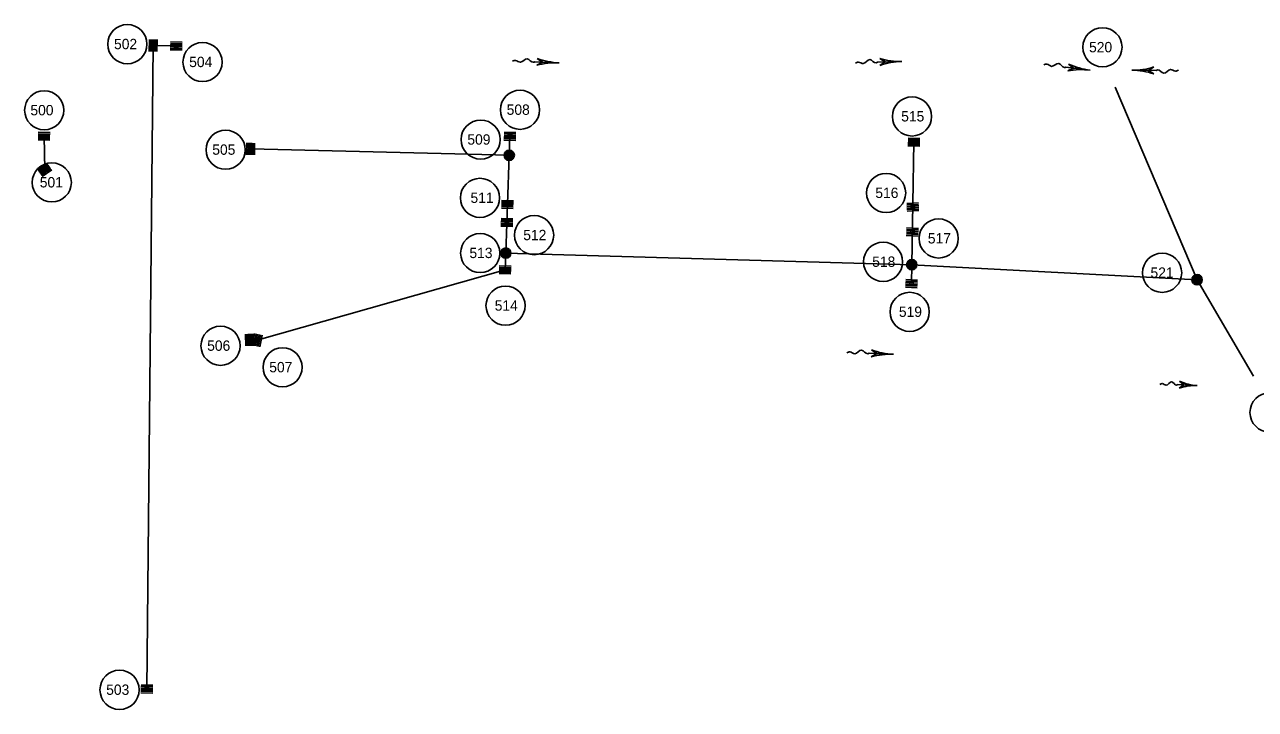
# Model space of a CAD drawing. Extents: x 594534 to 598564, y 225861 to 236229.
# Drawn here: x 594534 to 595247, y 230840 to 231238 of the extents above; entities that cross this region are included whole.
import ezdxf

# ---------------------------------------------------------------- set-up
doc = ezdxf.new("R2010")
doc.units = 0
for name, color, linetype in [('P_AREA', 7, 'Continuous'), ('P_DRN_Flow', 7, 'Continuous'), ('P_DRN_Inlet', 7, 'Continuous'), ('P_DRN_SS_MH', 7, 'Continuous'), ('P_DRN_SS_UG', 7, 'Continuous'), ('P_DRN_Text', 7, 'Continuous')]:
    doc.layers.add(name, color=color, linetype=linetype)

msp = doc.modelspace()

# ---------------------------------------------------------------- linework, layer by layer
at = {"layer": 'P_AREA'}
for p, q in [((594814.51, 231158.91), (594814.55, 231159.91)), ((594814.26, 231151.16), (594814.29, 231152.16))]:
    msp.add_line(p, q, dxfattribs=at)
at = {"layer": 'P_DRN_Flow'}
for p, q in [((594843.53, 231215.58), (594829.42, 231216.21)), ((595042.34, 231216.42), (595028.21, 231216.02)), ((595042.34, 231216.42), (595028.21, 231216.02)), ((595042.34, 231216.42), (595028.21, 231216.02)), ((595151.44, 231211.3), (595137.43, 231213.11)), ((595175.67, 231211.31), (595189.8, 231211.18)), ((595037.43, 231046.45), (595023.32, 231047.08)), ((595213.52, 231028.34), (595202.25, 231028.84))]:
    msp.add_line(p, q, dxfattribs=at)
for points in [[(594830.66, 231214.15), (594833.94, 231216.01), (594830.83, 231218.15)], [(595029.6, 231214.06), (595032.74, 231216.15), (595029.48, 231218.05)], [(595029.6, 231214.06), (595032.74, 231216.15), (595029.48, 231218.05)], [(595029.6, 231214.06), (595032.74, 231216.15), (595029.48, 231218.05)], [(595138.5, 231210.95), (595141.93, 231212.53), (595139, 231214.92)], [(595188.48, 231213.2), (595185.27, 231211.23), (595188.45, 231209.2)], [(595024.56, 231045.02), (595027.84, 231046.88), (595024.73, 231049.02)], [(595203.22, 231026.8), (595205.86, 231028.68), (595203.39, 231030.79)]]:
    msp.add_lwpolyline(points, dxfattribs=at)
for centre, start, end in [((594841.67, 231173.67), 87.45551, 105.21783), ((594845.39, 231257.5), 249.69319, 267.45551), ((595041.14, 231258.36), 253.87176, 271.63408), ((595041.14, 231258.36), 253.87176, 271.63408), ((595041.14, 231258.36), 253.87176, 271.63408), ((595043.53, 231174.48), 91.63408, 109.3964), ((595043.53, 231174.48), 91.63408, 109.3964), ((595043.53, 231174.48), 91.63408, 109.3964), ((595156.81, 231252.91), 244.8924, 262.65472), ((595176.03, 231253.26), 269.5075, 287.26982), ((595146.08, 231169.69), 82.65472, 100.41704), ((595175.31, 231169.35), 71.74518, 89.5075), ((595039.29, 231088.37), 249.69319, 267.45551), ((595035.57, 231004.54), 87.45551, 105.21783)]:
    msp.add_arc(centre, 41.96, start, end, dxfattribs=at)
for centre, major_axis, start_param, end_param in [((595211.66, 230986.43), (1.86, 41.92), 0, 0.310011), ((595215.38, 231070.26), (-1.86, -41.92), 5.973174, 6.283185)]:
    msp.add_ellipse(centre, major_axis=major_axis, ratio=0.798772, start_param=start_param, end_param=end_param, dxfattribs=at)
for points in [[(594829.42, 231216.21), (594828.62, 231215.93), (594825.1, 231217.97), (594821.08, 231215.95), (594818.3, 231217.02), (594816.54, 231216.47)], [(595028.21, 231216.02), (595027.44, 231215.68), (595023.77, 231217.46), (595019.91, 231215.16), (595017.06, 231216.02), (595015.36, 231215.34)], [(595028.21, 231216.02), (595027.44, 231215.68), (595023.77, 231217.46), (595019.91, 231215.16), (595017.06, 231216.02), (595015.36, 231215.34)], [(595028.21, 231216.02), (595027.44, 231215.68), (595023.77, 231217.46), (595019.91, 231215.16), (595017.06, 231216.02), (595015.36, 231215.34)], [(595137.43, 231213.11), (595136.61, 231212.9), (595133.27, 231215.23), (595129.1, 231213.55), (595126.42, 231214.84), (595124.62, 231214.44)], [(595189.8, 231211.18), (595190.59, 231211.49), (595194.18, 231209.58), (595198.12, 231211.74), (595200.94, 231210.77), (595202.67, 231211.39)], [(595023.32, 231047.08), (595022.52, 231046.8), (595018.99, 231048.84), (595014.98, 231046.82), (595012.19, 231047.89), (595010.44, 231047.34)], [(595202.25, 231028.84), (595201.61, 231028.56), (595198.81, 231030.57), (595195.58, 231028.51), (595193.37, 231029.55), (595191.96, 231028.99)]]:
    msp.add_spline(points, degree=3, dxfattribs=at)
at = {"layer": 'P_DRN_Inlet'}
for p, q in [((594605.83, 231222.25), (594605.95, 231229.13)), ((594606.73, 231222.24), (594606.85, 231229.11)), ((594607.63, 231222.22), (594607.75, 231229.09)), ((594608.53, 231222.2), (594608.65, 231229.08)), ((594609.43, 231222.19), (594609.55, 231229.06)), ((594610.33, 231222.17), (594610.45, 231229.05)), ((594618.12, 231226.83), (594625, 231226.7)), ((594618.14, 231227.73), (594625.01, 231227.6)), ((594618.06, 231223.23), (594624.93, 231223.1)), ((594618.07, 231224.13), (594624.95, 231224)), ((594618.09, 231225.03), (594624.96, 231224.9)), ((594618.11, 231225.93), (594624.98, 231225.8)), ((594541.4, 231170.82), (594548.27, 231170.7)), ((594541.42, 231171.72), (594548.29, 231171.6)), ((594541.43, 231172.62), (594548.31, 231172.49)), ((594541.45, 231173.52), (594548.32, 231173.39)), ((594541.47, 231174.42), (594548.34, 231174.29)), ((594541.48, 231175.32), (594548.36, 231175.19)), ((594811.56, 231170.71), (594818.43, 231170.59)), ((594811.58, 231171.61), (594818.45, 231171.49)), ((594811.59, 231172.51), (594818.47, 231172.39)), ((594811.61, 231173.41), (594818.48, 231173.29)), ((594811.63, 231174.31), (594818.5, 231174.18)), ((594811.64, 231175.21), (594818.52, 231175.08)), ((595045.9, 231170.1), (595052.77, 231169.98)), ((595045.91, 231171), (595052.78, 231170.88)), ((595045.93, 231171.9), (595052.8, 231171.78)), ((594662.36, 231162.25), (594662.48, 231169.12)), ((594663.26, 231162.23), (594663.38, 231169.11)), ((594664.16, 231162.22), (594664.28, 231169.09)), ((594665.06, 231162.2), (594665.18, 231169.08)), ((594665.96, 231162.19), (594666.08, 231169.06)), ((594666.86, 231162.17), (594666.98, 231169.04)), ((595045.85, 231167.4), (595052.72, 231167.28)), ((595045.86, 231168.3), (595052.74, 231168.18)), ((595045.88, 231169.2), (595052.75, 231169.08)), ((594546.8, 231157.26), (594541.2, 231153.27)), ((594547.33, 231156.52), (594541.73, 231152.53)), ((594547.85, 231155.79), (594542.25, 231151.8)), ((594548.37, 231155.06), (594542.77, 231151.07)), ((594548.89, 231154.32), (594543.29, 231150.33)), ((594549.41, 231153.59), (594543.81, 231149.6)), ((594810.15, 231133.93), (594817.02, 231133.81)), ((594810.16, 231134.83), (594817.04, 231134.71)), ((594810.18, 231135.73), (594817.05, 231135.61)), ((595045.13, 231134.02), (595052, 231134.35)), ((594810.1, 231131.23), (594816.97, 231131.11)), ((594810.11, 231132.13), (594816.99, 231132.01)), ((594810.13, 231133.03), (594817, 231132.91)), ((595045.17, 231133.12), (595052.04, 231133.45)), ((595045.22, 231132.23), (595052.08, 231132.55)), ((595045.26, 231131.33), (595052.13, 231131.65)), ((595045.3, 231130.43), (595052.17, 231130.75)), ((595045.35, 231129.53), (595052.21, 231129.85)), ((594809.8, 231120.74), (594816.68, 231120.61)), ((594809.82, 231121.64), (594816.69, 231121.51)), ((594809.84, 231122.54), (594816.71, 231122.41)), ((594809.85, 231123.44), (594816.73, 231123.31)), ((594809.87, 231124.34), (594816.74, 231124.21)), ((594809.89, 231125.24), (594816.76, 231125.11)), ((595045.11, 231119.87), (595051.98, 231119.5)), ((595044.87, 231115.37), (595051.73, 231115)), ((595044.92, 231116.27), (595051.78, 231115.9)), ((595044.96, 231117.17), (595051.83, 231116.8)), ((595045.01, 231118.07), (595051.88, 231117.7)), ((595045.06, 231118.97), (595051.93, 231118.6)), ((594808.76, 231093.25), (594815.64, 231093.13)), ((594808.78, 231094.15), (594815.65, 231094.03)), ((594808.8, 231095.05), (594815.67, 231094.93)), ((594808.81, 231095.95), (594815.69, 231095.82)), ((594808.83, 231096.85), (594815.7, 231096.72)), ((594808.85, 231097.75), (594815.72, 231097.62)), ((595044.35, 231085.39), (595051.21, 231085.02)), ((595044.4, 231086.29), (595051.26, 231085.92)), ((595044.45, 231087.19), (595051.31, 231086.82)), ((595044.49, 231088.09), (595051.36, 231087.72)), ((595044.54, 231088.99), (595051.41, 231088.62)), ((595044.59, 231089.89), (595051.46, 231089.52)), ((594661.68, 231058.21), (594661.86, 231051.34)), ((594662.58, 231058.23), (594662.76, 231051.36)), ((594663.48, 231058.26), (594663.66, 231051.38)), ((594664.38, 231058.28), (594664.56, 231051.41)), ((594665.28, 231058.3), (594665.46, 231051.43)), ((594666.96, 231058.49), (594665.58, 231051.76)), ((594666.18, 231058.33), (594666.36, 231051.46)), ((594667.84, 231058.31), (594666.46, 231051.58)), ((594668.72, 231058.13), (594667.35, 231051.4)), ((594669.6, 231057.96), (594668.23, 231051.22)), ((594670.48, 231057.78), (594669.11, 231051.04)), ((594671.36, 231057.6), (594669.99, 231050.86)), ((594601.04, 230850.02), (594607.91, 230849.89)), ((594601.05, 230850.92), (594607.93, 230850.79)), ((594601.07, 230851.82), (594607.94, 230851.69)), ((594601.09, 230852.72), (594607.96, 230852.59)), ((594601.1, 230853.62), (594607.98, 230853.49)), ((594601.12, 230854.52), (594607.99, 230854.39))]:
    msp.add_line(p, q, dxfattribs=at)
for points in [[(594609.12, 231224.63), (594609.16, 231226.63), (594607.16, 231226.67), (594607.12, 231224.67)], [(594620.52, 231224.44), (594622.52, 231224.4), (594622.55, 231226.4), (594620.55, 231226.43)], [(594543.86, 231172.03), (594545.86, 231171.99), (594545.9, 231173.99), (594543.9, 231174.03)], [(594814.02, 231171.92), (594816.02, 231171.88), (594816.06, 231173.88), (594814.06, 231173.92)], [(595048.31, 231168.6), (595050.31, 231168.57), (595050.34, 231170.57), (595048.34, 231170.6)], [(594665.65, 231164.63), (594665.69, 231166.63), (594663.69, 231166.66), (594663.65, 231164.67)], [(594545.54, 231154.82), (594543.91, 231153.66), (594545.08, 231152.03), (594546.7, 231153.19)], [(594812.56, 231132.44), (594814.56, 231132.4), (594814.59, 231134.4), (594812.59, 231134.44)], [(595047.72, 231130.89), (595049.72, 231130.99), (595049.62, 231132.99), (595047.63, 231132.89)], [(594812.26, 231121.94), (594814.26, 231121.9), (594814.3, 231123.9), (594812.3, 231123.94)], [(595047.37, 231116.49), (595049.37, 231116.38), (595049.47, 231118.38), (595047.48, 231118.49)], [(594811.22, 231094.46), (594813.22, 231094.42), (594813.26, 231096.42), (594811.26, 231096.46)], [(595046.85, 231086.51), (595048.85, 231086.4), (595048.95, 231088.4), (595046.96, 231088.51)], [(594662.99, 231055.81), (594663.05, 231053.81), (594665.05, 231053.86), (594664.99, 231055.86)], [(594667.69, 231055.86), (594667.29, 231053.9), (594669.25, 231053.5), (594669.65, 231055.46)], [(594603.5, 230851.22), (594605.5, 230851.19), (594605.53, 230853.19), (594603.53, 230853.22)]]:
    msp.add_lwpolyline(points, close=True, dxfattribs=at)
at = {"layer": 'P_DRN_SS_MH'}
for centre, radius in [((594814.62, 231161.93), 2.98), ((594814.62, 231161.93), 2.4), ((594814.62, 231161.93), 1.8), ((594814.62, 231161.93), 1.2), ((594814.62, 231161.93), 0.6), ((594812.62, 231105.18), 2.98), ((594812.62, 231105.18), 2.4), ((594812.62, 231105.18), 1.8), ((594812.62, 231105.18), 1.2), ((594812.62, 231105.18), 0.6), ((595048.09, 231098.47), 2.98), ((595048.09, 231098.47), 2.4), ((595048.09, 231098.47), 1.8), ((595048.09, 231098.47), 1.2), ((595048.09, 231098.47), 0.6), ((595213.5, 231089.73), 2.98), ((595213.5, 231089.73), 2.4), ((595213.5, 231089.73), 1.8), ((595213.5, 231089.73), 1.2), ((595213.5, 231089.73), 0.6)]:
    msp.add_circle(centre, radius, dxfattribs=at)
at = {"layer": 'P_DRN_SS_UG'}
for p, q in [((594608.14, 231225.65), (594604.52, 230852.21)), ((594621.58, 231225.42), (594608.18, 231225.65)), ((595165.98, 231201.47), (595213.5, 231089.73)), ((595165.98, 231201.47), (595213.5, 231089.73)), ((594545.31, 231153.43), (594544.88, 231173.01)), ((594815.01, 231173.15), (594812.62, 231105.18)), ((595049.32, 231169.59), (595048.09, 231098.47)), ((594664.67, 231165.65), (594814.62, 231161.93)), ((594812.28, 231095.44), (594812.62, 231105.18)), ((594812.62, 231105.18), (595048.09, 231098.47)), ((595047.9, 231087.45), (595048.09, 231098.47)), ((595048.09, 231098.47), (595213.5, 231089.73)), ((594668.47, 231054.68), (594812.24, 231095.44)), ((595213.5, 231089.73), (595246.3, 231033.82)), ((594664.02, 231054.83), (594668.47, 231054.68))]:
    msp.add_line(p, q, dxfattribs=at)
at = {"layer": 'P_DRN_Text'}
for centre in [(594593.19, 231226.43), (595158.65, 231224.63), (594636.78, 231216.04), (594544.97, 231188.06), (594820.9, 231188.34), (595048.22, 231184.49), (594650.17, 231165.17), (594798.1, 231171.05), (594549.37, 231146.21), (594797.67, 231137.22), (595033.21, 231140.08), (594829.05, 231115.6), (595063.67, 231113.69), (594797.82, 231105.21), (595031.42, 231100.12), (595193.25, 231093.76), (594812.5, 231074.7), (595046.88, 231071.09), (594647.22, 231051.41), (594683.21, 231038.92), (595255.55, 231012.69), (594588.66, 230851.75)]:
    msp.add_circle(centre, 11.36, dxfattribs=at)

# ---------------------------------------------------------------- texts
for s, p in [('502', (594585.46, 231223.51)), ('520', (595150.89, 231221.71)), ('504', (594629.05, 231213.12)), ('500', (594536.97, 231185.14)), ('508', (594813.16, 231185.42)), ('515', (595041.95, 231181.57)), ('509', (594790.36, 231168.13)), ('505', (594642.44, 231162.25)), ('501', (594542.4, 231143.29)), ('516', (595026.94, 231137.16)), ('511', (594792.16, 231134.3)), ('512', (594822.78, 231112.68)), ('517', (595057.4, 231110.77)), ('513', (594791.55, 231102.29)), ('518', (595025.15, 231097.21)), ('521', (595186.51, 231090.85)), ('514', (594806.23, 231071.78)), ('519', (595040.61, 231068.17)), ('506', (594639.48, 231048.49)), ('507', (594675.48, 231036)), ('503', (594580.92, 230848.83))]:
    msp.add_text(s, height=6, dxfattribs=at).set_placement(p)

doc.saveas('drawing.dxf')
